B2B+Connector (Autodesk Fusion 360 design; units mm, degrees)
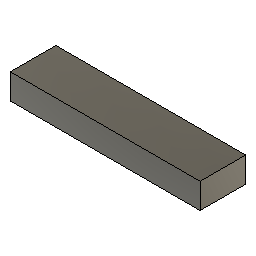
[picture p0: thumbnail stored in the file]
sketch "Sketch1" plane through (0, 0, 0) normal (0, 0, 1) x axis (1, 0, 0)
  line L1 (-7.5, 0) -> (0, 0)
  line L2 (-7.5, 1.8) -> (-7.5, 0)
  line L3 (0, 1.8) -> (-7.5, 1.8)
  line L4 (0, 0) -> (0, 1.8)
  point P1 (0, 0)
  point P2 (0, 0)
  point P5 (0, 1.8)
  point P3 (-7.5, 0)
  horizontal L1
  vertical L2
  horizontal L3
  vertical L4
  coincident P1 P2
  dimension "d2" distance P2 P5 = 1.8 (= "( 1.8 * Ratio ) * 1 mm")
  dimension "d3" distance P2 P3 = 7.5 (= "( 7.5 * Ratio ) * 1 mm")
extrude "Extrude1" new body sketch "Sketch1" along normal blind 1 (= "( 1 * Ratio ) * 1 mm")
